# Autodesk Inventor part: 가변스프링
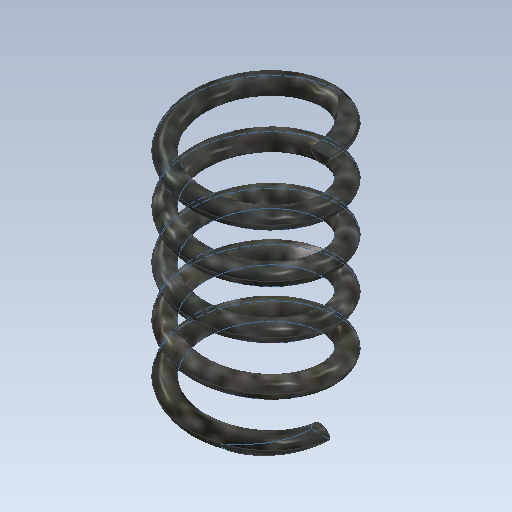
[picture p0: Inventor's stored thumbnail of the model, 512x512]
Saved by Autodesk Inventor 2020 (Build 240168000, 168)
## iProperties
Created: 2020-12
Part Number: 가변스프링
Material: 강철
Document SubType Name: Modeling
Designer: USER
Density: 7.85 g/cm^3
Appearance: 플레이트
Mass: 5.33662 g
Surface Area: 13.8263 cm^2
Volume: 0.679824 cm^3
Author: USER
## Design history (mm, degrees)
sketch "스케치1"
  geometry: L1 (0, 0)-(7, 0); L2 (7, 0)-(7, 26.5); L3 (7, 26.5)-(0, 26.5); L4 (0, 26.5)-(0, 0); C1 r 1 at (7, 0)
  constraints: 8 end point, 2 parallel, 1 centre point, 1 coincident, 1 horizontal, 1 perpendicular
  dimensions: "d0" = 14 diameter of L2 L4; "d1" = 26.5 distance of L1.end L2.end (derived); "d2" = 2 diameter of C1
feature "코일1" sketch "스케치1" pitch "d3" = 10; turns "d5" = 5; dims "d4" = 26.5 (= d1), "d6" = 0, angle "d7" = 90 deg, angle "d8" = 90 deg, "d9" = 0, "d10" = 0
sketch "스케치2"
  geometry: L1 (-6, 0)-(-8, 0) reference; L2 (-6, 0)-(-8, 0) reference; 1 further point
  constraints: 2 horizontal alignment
extrude "돌출1" cut sketch "스케치2" distance "d11" = 10; taper "d12" = 0 deg
node "작업 평면1"
sketch "스케치3"
  geometry: L1 (-1, 0)-(1, 0) reference; 1 further point
  constraints: 1 horizontal alignment
extrude "돌출2" cut sketch "스케치3" distance "d14" = 10; taper "d15" = 0 deg
node "솔리드1"
node "절단 모서리 투영1"
node "절단 모서리 투영2"
node "절단 모서리 투영3"
other parameters: "d13" = 90 deg
